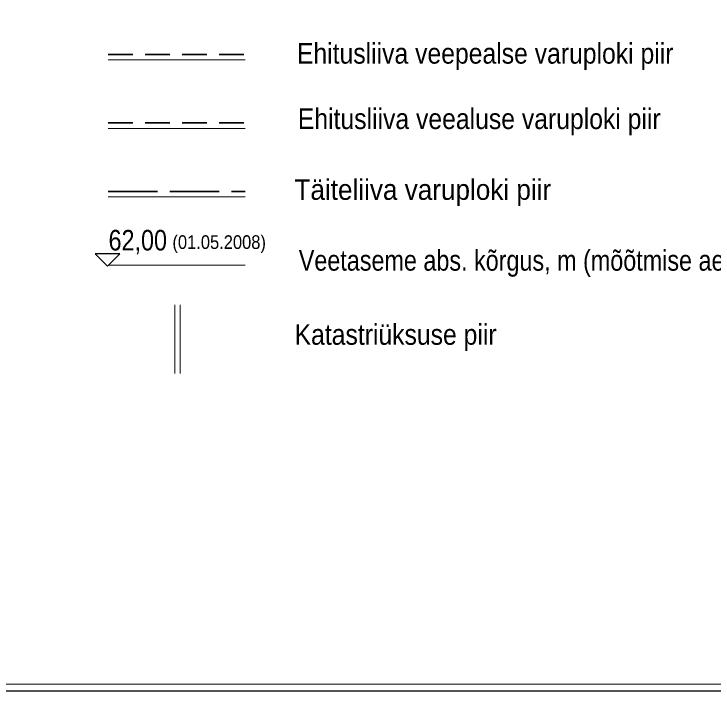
# Model space of a CAD drawing. Extents: x 640104 to 640970, y 6442278 to 6442689.
# Drawn here: x 640594.7 to 640696.8, y 6442282.5 to 6442381.4 of the extents above; entities that cross this region are included whole.
import ezdxf
from ezdxf.enums import TextEntityAlignment as Align

# ---------------------------------------------------------------- set-up
doc = ezdxf.new("R2010")
doc.units = 0
doc.header["$LTSCALE"] = 1.2
doc.linetypes.add('LONG_DASHED', pattern=[7.5, 6, -1.5])
doc.linetypes.add('MEDIUM_DASHED', pattern=[4.5, 3, -1.5])
doc.layers.add('50', color=7, linetype='Continuous', lineweight=13)

msp = doc.modelspace()

# ---------------------------------------------------------------- linework, layer by layer
at = {"layer": '50', "linetype": 'MEDIUM_DASHED', "lineweight": 35}
for p, q in [((640608.44, 6442375.5), (640628.44, 6442375.5)), ((640608.44, 6442365.5), (640628.44, 6442365.5))]:
    msp.add_line(p, q, dxfattribs=at)
at = {"layer": '50'}
for p, q in [((640608.44, 6442374.7), (640628.44, 6442374.7)), ((640608.44, 6442364.7), (640628.44, 6442364.7)), ((640608.44, 6442354.7), (640628.44, 6442354.7)), ((640608.44, 6442344.7), (640628.44, 6442344.7)), ((640618.17, 6442328.91), (640618.17, 6442338.91)), ((640618.97, 6442328.91), (640618.97, 6442338.91))]:
    msp.add_line(p, q, dxfattribs=at)
at = {"layer": '50', "linetype": 'LONG_DASHED', "lineweight": 35}
msp.add_line((640608.44, 6442355.5), (640628.44, 6442355.5), dxfattribs=at)
at = {"layer": '50', "lineweight": 25}
for points in [[(640103.56, 6442688.99), (640970.3, 6442688.99), (640970.3, 6442282.54), (640103.56, 6442282.54)], [(640606.56, 6442346.4), (640608.35, 6442344.59), (640610.13, 6442346.39)]]:
    msp.add_lwpolyline(points, close=True, dxfattribs=at)
at = {"layer": '50'}
msp.add_lwpolyline([(640104.56, 6442687.99), (640969.3, 6442687.99), (640969.3, 6442283.54), (640104.56, 6442283.54)], close=True, dxfattribs=at)

# ---------------------------------------------------------------- texts
for s, height, width, p in [('Ehitusliiva veepealse varuploki piir', 3, 0.9, (640663.495, 6442374.15)), ('Ehitusliiva veealuse varuploki piir', 3, 0.9, (640662.625, 6442364.6)), ('Täiteliiva varuploki piir', 3, 0.95, (640654.39, 6442354.26)), ('62,00', 3, 0.85, (640612.765, 6442346.87)), ('(01.05.2008)', 2, 0.9, (640624.65, 6442347.09)), ('Veetaseme abs. kõrgus, m (mõõtmise aeg)', 3, 0.85, (640668.87, 6442343.92)), ('Katastriüksuse piir', 3, 0.9, (640650.41, 6442333.1))]:
    msp.add_text(s, height=height, dxfattribs=dict(at, width=width)).set_placement(p, align=Align.CENTER)

doc.saveas('drawing.dxf')
